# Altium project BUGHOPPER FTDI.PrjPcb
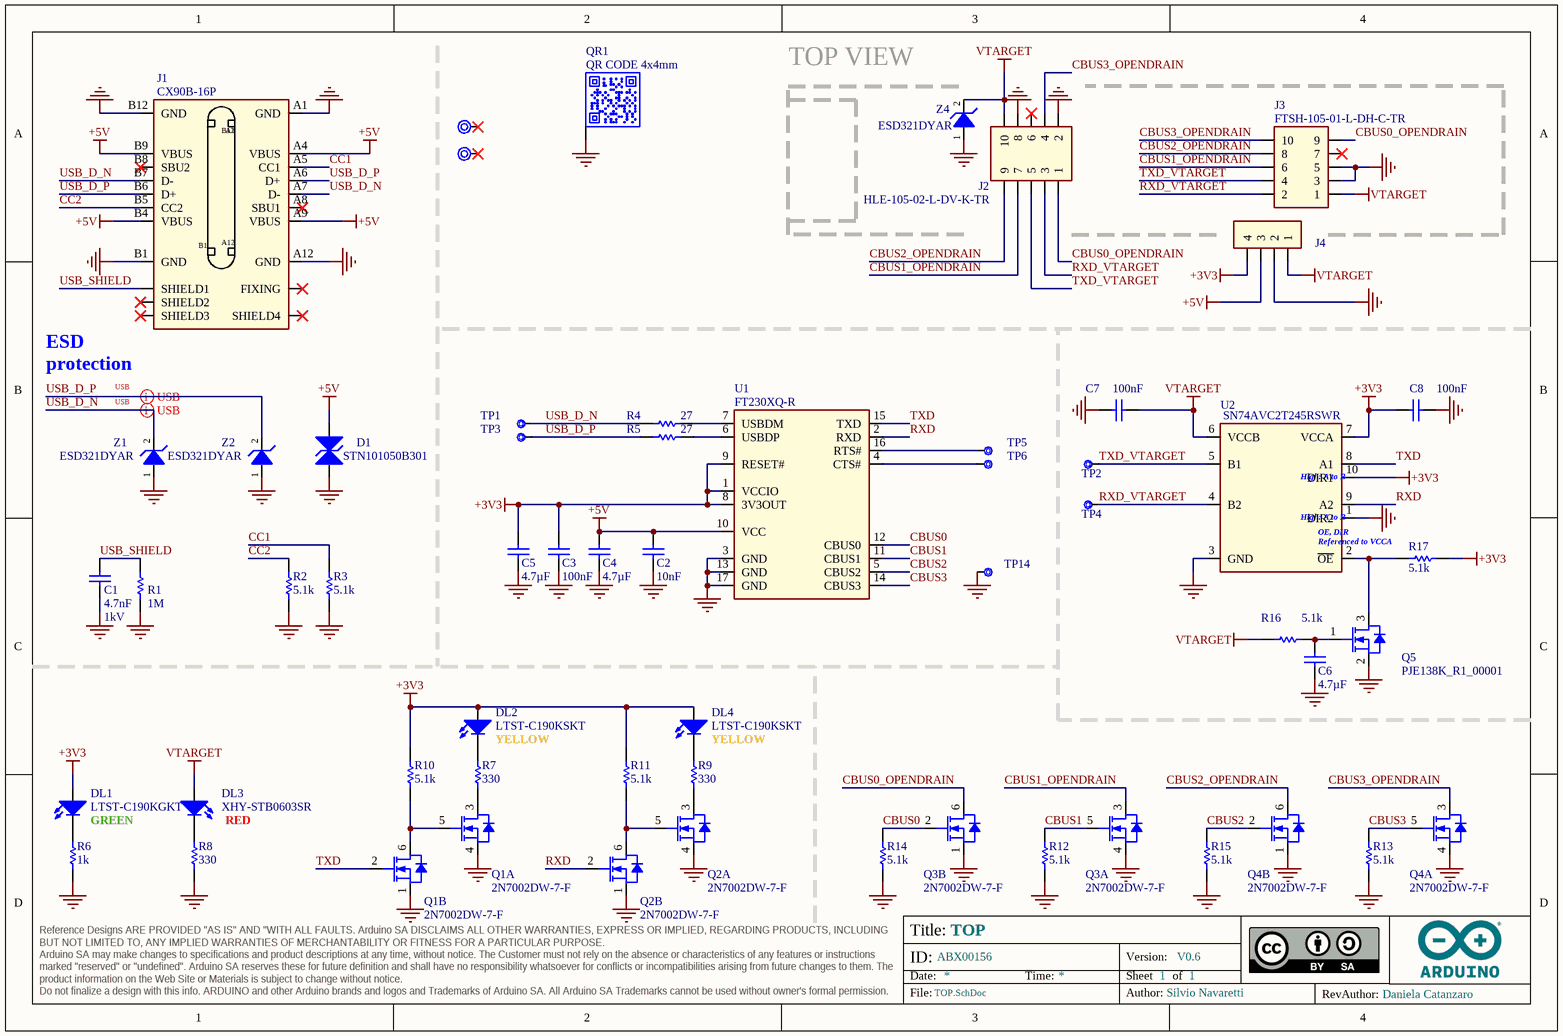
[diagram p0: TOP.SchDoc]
ASSEMBLY_BGA: _; ASSEMBLY_PRESSFIT: _; ASSEMBLY_SMD: X; ASSEMBLY_THT: _; BOARD_CODENAME: BUGHOPPER; BOARD_INFO_AUTHOR: Silvio Navaretti; BOARD_INFO_AUTHOR_REV: Daniela Catanzaro; BOARD_INFO_Er: _; BOARD_INFO_FLEX: _; BOARD_INFO_FR4: X; BOARD_INFO_FR4_HTG: _; BOARD_INFO_IPC1: _; BOARD_INFO_IPC2: X; BOARD_INFO_IPC3: _; BOARD_INFO_IPC_NA: _; BOARD_INFO_NUMBER_OF_LAYERS: 4; BOARD_INFO_PCB_SIZE: 35x11mm; BOARD_INFO_POLYMIDE: _; BOARD_INFO_RIGID: X; BOARD_INFO_RIGID/FLEX: _; BOARD_INFO_TBD: _; BOARD_INFO_THICKNESS: 1.6mm; DRILLS_BLIND: _; DRILLS_BURIED: _; DRILLS_COPPER_FILLING: _; DRILLS_FULL: X; DRILLS_LASER: _; DRILLS_PRESSFIT: _; DRILLS_RESIN_FILLING: _; DRILLS_SLOT: _; DRILLS_SOLDER_FILLING: X; FINISH_ADJUSTMENTS: _; FINISH_EDGE_PLATING: _; FINISH_ENIG: X; FINISH_HAL: _; FINISH_HAL_LF: _; FINISH_NI/AU: _; FINISH_SILK_BOTTOM: X; FINISH_SILK_COLOR: WHITE; FINISH_SILK_TOP: X; FINISH_SN/PB: _; FINISH_SOLDERMASK_BOTTOM: X; FINISH_SOLDERMASK_COLOR: BLUE; FINISH_SOLDERMASK_PEELABLE_BOTTOM: _; FINISH_SOLDERMASK_PEELABLE_COLOR: _; FINISH_SOLDERMASK_PEELABLE_TOP: _; FINISH_SOLDERMASK_TOP: X; FINISH_TABS: _; FINISH_TBD: _; INSULATION_MIN_INNER: 0.127mm; INSULATION_MIN_OUTER: 0.127mm; PANEL_MILLING: X; PANEL_NOT_REQUESTED: _; PANEL_NUMBER_OF_FIGURES: 16; PANEL_PROVIDED: X; PANEL_REQUESTED: _; PANEL_SCORING: X; PANEL_SIZE: 168x100mm; PANEL_TABS: _; PROTOTYPE_NAME: SULLA; SKU: ABX00156; TRACK_MIN_WIDTH_INNER: 0.127mm; TRACK_MIN_WIDTH_OUTER: 0.127mm; Version: V0.6; VIA_1: _; VIA_1_HOLE_MM: _; VIA_1_PAD_MM: _; VIA_2: _; VIA_2_HOLE_MM: _; VIA_2_PAD_MM: _; VIA_3: _; VIA_3_HOLE_MM: _; VIA_3_PAD_MM: _; VIA_4: _; VIA_4_HOLE_MM: _; VIA_4_PAD_MM: _; VIA_5: _; VIA_5_HOLE_MM: _; VIA_5_PAD_MM: _; VIA_THROUGH: X; VIA_THROUGH_HOLE_MM: 0.2; VIA_THROUGH_PAD_MM: 0.4
1 sheet, 54 parts. Net scope: hierarchical (ports join the sheet entries above them; power ports are global).
Board files: PCB.PcbDoc, PANEL.PcbDoc

## Sheet TOP.SchDoc: TOP
size A4; Revision: V0.6; SheetNumber: 1; SheetTotal: 1

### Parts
C1  value 4.7nF  Voltage: 1kV  [CAP-0805]  (hidden comment: FV21X472K102ECG)
C2  value 10nF  [CAP-0402]  (hidden comment: C1005B103K500NT)
C3  value 100nF  [CAP-0201]  (hidden comment: CL03A104KP3NNNC)
C4  value 4.7µF  [CAP-0402]  (hidden comment: C1005A475M6R3NT)
C5  value 4.7µF  [CAP-0402]  (hidden comment: C1005A475M6R3NT)
C6  value 4.7µF  [CAP-0402]  (hidden comment: C1005A475M6R3NT)
C7  value 100nF  [CAP-0201]  (hidden comment: CL03A104KP3NNNC)
C8  value 100nF  [CAP-0201]  (hidden comment: CL03A104KP3NNNC)
D1  STN101050B301  [X1-DFN1006-2]
DL1  LTST-C190KGKT  [LEDC1608X80N-AK]
DL2  LTST-C190KSKT  [LEDC1608X80N-AK]
DL3  XHY-STB0603SR  [LEDC1608X80N-AK]
DL4  LTST-C190KSKT  [LEDC1608X80N-AK]
Fiducial_3  Fiducial mark 1mm with 2mm solder  [Fiducial mark 1mm with circle-Footprint-1]  (value not drawn)  (no BOM)
Fiducial_4  Fiducial mark 1mm with 2mm solder  [Fiducial mark 1mm with circle-Footprint-1]  (value not drawn)  (no BOM)
J1  CX90B-16P  [CX90B-16P-Footprint-1]
J2  HLE-105-02-L-DV-K-TR  [HLE-105-02-L-DV-BE-K-TR]
J3  FTSH-105-01-L-DH-C-TR  [FTSH-105-01-L-DH-C-TR]
J4  HEADER TH 2.54mm VERT. 1x004POS  [PIN HEADER 2.54mm VERT. 1x4POS-Footprint-1]  (value not drawn)
Q1  2N7002DW-7-F  [SOT363]  (parts A,B of 2)
Q2  2N7002DW-7-F  [SOT363]  (parts A,B of 2)
Q3  2N7002DW-7-F  [SOT363]  (parts A,B of 2)
Q4  2N7002DW-7-F  [SOT363]  (parts A,B of 2)
Q5  PJE138K_R1_00001  [SOT-523]
QR1  QR CODE 4x4mm  [QR CODE 4x4mm]  (no BOM)
R1  value 1M  [RES-0402]  (hidden comment: CRCW04021M00FKED)
R2  value 5.1k  [RES-0201]  (hidden comment: RC0201FR-075K1L)
R3  value 5.1k  [RES-0201]  (hidden comment: RC0201FR-075K1L)
R4  value 27  [RES-0201]  (hidden comment: CRCW020127R0FNED)
R5  value 27  [RES-0201]  (hidden comment: CRCW020127R0FNED)
R6  value 1k  [RES-0201]  (hidden comment: RC0201FR-071KL)
R7  value 330  [RES-0201]  (hidden comment: AC0201FR-07330RL)
R8  value 330  [RES-0201]  (hidden comment: AC0201FR-07330RL)
R9  value 330  [RES-0201]  (hidden comment: AC0201FR-07330RL)
R10  value 5.1k  [RES-0201]  (hidden comment: RC0201FR-075K1L)
R11  value 5.1k  [RES-0201]  (hidden comment: RC0201FR-075K1L)
R12  value 5.1k  [RES-0201]  (hidden comment: RC0201FR-075K1L)
R13  value 5.1k  [RES-0201]  (hidden comment: RC0201FR-075K1L)
R14  value 5.1k  [RES-0201]  (hidden comment: RC0201FR-075K1L)
R15  value 5.1k  [RES-0201]  (hidden comment: RC0201FR-075K1L)
R16  value 5.1k  [RES-0201]  (hidden comment: RC0201FR-075K1L)
R17  value 5.1k  [RES-0201]  (hidden comment: RC0201FR-075K1L)
TP1  Test point 1.00mm  [TP-1.00MM]  (value not drawn)  (no BOM)
TP2  Test point 1.00mm  [TP-1.00MM]  (value not drawn)  (no BOM)
TP3  Test point 1.00mm  [TP-1.00MM]  (value not drawn)  (no BOM)
TP4  Test point 1.00mm  [TP-1.00MM]  (value not drawn)  (no BOM)
TP5  Test point 1.00mm  [TP-1.00MM]  (value not drawn)  (no BOM)
TP6  Test point 1.00mm  [TP-1.00MM]  (value not drawn)  (no BOM)
TP14  Test point 1.00mm  [TP-1.00MM]  (value not drawn)  (no BOM)
U1  FT230XQ-R  [FTDI QFN16 4x4mm pitch 0.65mm]
U2  SN74AVC2T245RSWR  [TI RSW RSW0010A UFQN 10 1.4x1.8mm]
Z1  ESD321DYAR  [ESD321DYAR]
Z2  ESD321DYAR  [ESD321DYAR]
Z4  ESD321DYAR  [ESD321DYAR]

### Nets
+3V3: C3.2 C5.2 C8.2 DL1.A DL2.A DL4.A J4.4 R10.2 R11.2 R17.1 U1.1(VCCIO) U1.8(3V3OUT) U1.9(RESET#) U2.7(VCCA) U2.10(DIR1)
+5V: C2.2 C4.2 D1.2(A2) J1.A4(VBUS) J1.A9(VBUS) J1.B4(VBUS) J1.B9(VBUS) J4.3 U1.10(VCC)
GND: C1.1 C2.1 C3.1 C4.1 C5.1 C6.1 C7.1 C8.1 D1.1(A1) J1.A1(GND) J1.A12(GND) J1.B1(GND) J1.B12(GND) J2.2 J2.8 J3.3 J3.5 J4.2 Q1.1(S) Q1.4(S) Q2.1(S) Q2.4(S) Q3.1(S) Q3.4(S) Q4.1(S) Q4.4(S) Q5.2(S) QR1.PAD R1.1 R2.1 R3.1 R6.1 R8.1 R12.1 R13.1 R14.1 R15.1 TP14.X U1.3(GND) U1.13(GND) U1.17(GND) U2.1(DIR2) U2.3(GND) Z1.1 Z2.1 Z4.1
VTARGET: C7.2 DL3.A J2.10 J3.1 J4.1 R16.2 U2.6(VCCB) Z4.2
CBUS0: Q3.2(G) R14.2 U1.12(CBUS0)  [project net CBUS0_1]
CBUS0_OPENDRAIN: J2.1 J3.9 Q3.6(D)  [project net CBUS0_OPENDRAIN_1]
CBUS1: Q3.5(G) R12.2 U1.11(CBUS1)  [project net CBUS1_1]
CBUS1_OPENDRAIN: J2.7 J3.6 Q3.3(D)  [project net CBUS1_OPENDRAIN_1]
CBUS2: Q4.2(G) R15.2 U1.5(CBUS2)  [project net CBUS2_1]
CBUS2_OPENDRAIN: J2.9 J3.8 Q4.6(D)  [project net CBUS2_OPENDRAIN_1]
CBUS3: Q4.5(G) R13.2 U1.14(CBUS3)  [project net CBUS3_1]
CBUS3_OPENDRAIN: J2.4 J3.10 Q4.3(D)  [project net CBUS3_OPENDRAIN_1]
CC1: J1.A5(CC1) R3.2  [project net CC1_1]
CC2: J1.B5(CC2) R2.2  [project net CC2_1]
RXD: Q2.2(G) U1.2(RXD) U2.9(A2)  [project net RXD_1]
RXD_VTARGET: J2.3 J3.2 TP4.X U2.4(B2)  [project net RXD_VTARGET_1]
TXD: Q1.2(G) U1.15(TXD) U2.8(A1)  [project net TXD_1]
TXD_VTARGET: J2.5 J3.4 TP2.X U2.5(B1)  [project net TXD_VTARGET_1]
USB_D_N: J1.A7(D-) J1.B7(D-) R4.2 TP1.X Z1.2  [project net USB_D_N_1]
USB_D_P: J1.A6(D+) J1.B6(D+) R5.2 TP3.X Z2.2  [project net USB_D_P_1]
USB_SHIELD: C1.2 J1.SHIELD1 R1.2  [project net USB_SHIELD_1]
NetC6_2: C6.2 Q5.1(G) R16.1
NetDL1_C: DL1.C R6.2
NetDL2_C: DL2.C R7.2
NetDL3_C: DL3.C R8.2
NetDL4_C: DL4.C R9.2
NetQ1_3: Q1.3(D) R7.1
NetQ1_5: Q1.5(G) Q1.6(D) R10.1
NetQ2_3: Q2.3(D) R9.1
NetQ2_5: Q2.5(G) Q2.6(D) R11.1
NetQ5_3: Q5.3(D) R17.2 U2.2(~{OE})
NetR4_1: R4.1 U1.7(USBDM)
NetR5_1: R5.1 U1.6(USBDP)
NetTP5_X: TP5.X U1.16(RTS#)
NetTP6_X: TP6.X U1.4(CTS#)

Not connected (* = marked no-connect by the designer): Fiducial_3 1*; Fiducial_4 1*; J1 A8(SBU1)* B8(SBU2)* FIXING* SHIELD2* SHIELD3* SHIELD4*; J2 6*; J3 7*

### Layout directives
differential pair; differential pair class USB: USB_D_N_1, USB_D_P_1

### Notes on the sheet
- USB-C CONNECTOR
- TOP VIEW
- (near J1) ESD
  protection
- FTDI CHIP
- LEVEL TRANSLATOR
- LEDS
- YELLOW
- FTDI GPIO MOSFETS FOR OPEN DRAIN
- GREEN
- RED

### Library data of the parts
C1 = C0059-A.14: CAP CHIP 0805 4.7nF 10% 1000V X7R; Manufacturer: PSA Shenzen; Code Arduino: 0689
C2 = C0009-A.15: CAP CHIP 0402 10nF 10% 50V X7R; Manufacturer: Hottech; Code Arduino: 0165
C3 C7 C8 = C0113-A.6: CAP CHIP 0201 100nF 10% 10V X5R; Manufacturer: Samsung Electro-Mechanics; Code Arduino: C0113
C4-C6 = C0037-A.14: CAP CHIP 0402 4.7uF 20% 6V3 X5R; Manufacturer: Hottech; Code Arduino: 0833; Voltage: 6.3V
D1 = D0095-2: TVS BIDIRECTIONAL SMD Vr = 5V, Vbr min =  5.5V, 300W, DFN1006-2; Manufacturer: Eaton Electronics; Code Arduino: D0095; Vforward max: 0V; Ireverse max: 1µA
DL1 = L0009-A.6: LED SMD 0603 GREEN/568 15mcd 120^; Manufacturer: Liteon; Code Arduino: 2204
DL2 DL4 = L0008-A.6: LED SMD 0603 GIA588   8mcd 120^; Manufacturer: Liteon; Code Arduino: 2243
DL3 = L0024-A.4: LED SMD 0603 RED 625nm, water clear, 42 to 88 mcd, 120 degrees, 1.6x0.8x0.6mm; Manufacturer: Shenzen Corehy Technology; Code Arduino: L0024
Fiducial_3 Fiducial_4 = UT0024-A.6
J1 = J0272-A.3: CONN RCPT USB3.1 TYPEC 16POS SMD; Manufacturer: Hirose; Code Arduino: J0272
J2 = J0491-A.6: CONN HEADER FEMALE SMD 2.54mm 2x5POS DUAL ROW Top Entry heigth 3.66mm; Manufacturer: Samtec; Code Arduino: J0491
J3 = J0493-A.4: CONN HEADER FEMALE SMD 1.27mm 2x5POS HORIZONTAL DUAL ROW heigth 3.66mm; Manufacturer: Samtec; Code Arduino: J0493
J4 = J0162-A.6: Code Arduino: J0162
Q1-Q4 = T0011-A.12: MOSFET 2N-CH 60V 0.32A SOT363; Manufacturer: Diodes Inc.; Device Type: Mosfet 2N-CH SMD; Code Arduino: A5500
Q5 = T0062-A.2: MOSFET N-CH, 50V, ID 0.35A, Vth max 1.5V, SOT-523; Manufacturer: Panjit; Code Arduino: T0062
QR1 = QR-0001-A.5: QR CODE 4x4mm on layer 34 (This is not a component); Code Arduino: QRCODE_4x4mm
R1 = R0058-A.24: RES CHIP 0402 1M 1% 1/16W; Manufacturer: Vishay; Power: 62.5mW; Code Arduino: 0139; Temperature coefficient: 100ppm
R2 R3 = R0169-A.25: RES CHIP 0201 5k1 1% 1/20W; Manufacturer: Yageo; Power: 50mW; Code Arduino: R0169; Temperature coefficient: 200ppm
R4 R5 = R0197-A.20: RES CHIP 0201 27R 1% 1/20W; Manufacturer: Vishay; Code Arduino: R0197; Temperature coefficient: 200ppm; Power: 50mW
R6 = R0195-A.22: RES CHIP 0201 1k 1% 1/20W; Manufacturer: Yageo; Temperature coefficient: 200ppm; Power: 50mW; Code Arduino: R0195
R7-R9 = R0149-A.21: RES CHIP 0201 330R 1% 1/20W; Manufacturer: Yageo; Temperature coefficient: 200ppm; Power: 50mW; Code Arduino: R0149
R10-R17 = R0169-A.25: RES CHIP 0201 5k1 1% 1/20W; Manufacturer: Yageo; Temperature coefficient: 200ppm; Power: 50mW; Code Arduino: R0169
TP1-TP6 TP14 = UT0013-A.6: Manufacturer: This is not a component
U1 = U0428-A.3: IC FTDI USB to BASIC UART, +5V single supply, x4 IO, VCCIO 1V8 to 3V3, 3V3OUT internal LDO, QFN16 4x4mm; Code Arduino: U0428
U2 = U0430-A.2: IC TRANSLATOR LEVEL SHIFTER Unidirectional, 2BIT, VCCA and VCCB from 1.2V to 3.6V, Output enable, indipendent DIR pins, UQFN10 1.8x1.4mm; Manufacturer: Texas Instruments; Code Arduino: U0430
Z1 Z2 Z4 = P0022-5: TVS 1CH, 30kV, USB 2.0 ETH 10/100/1000, 0-3.6V, 0.9pF, IEC61000-4-5 peak current 80A surge 40W 6A, DC breakdown min 4.5V, SOD523 1.6x0.8mm; Manufacturer: Texas Instruments; Code Arduino: P0022

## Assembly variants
ABX00156: not fitted J4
